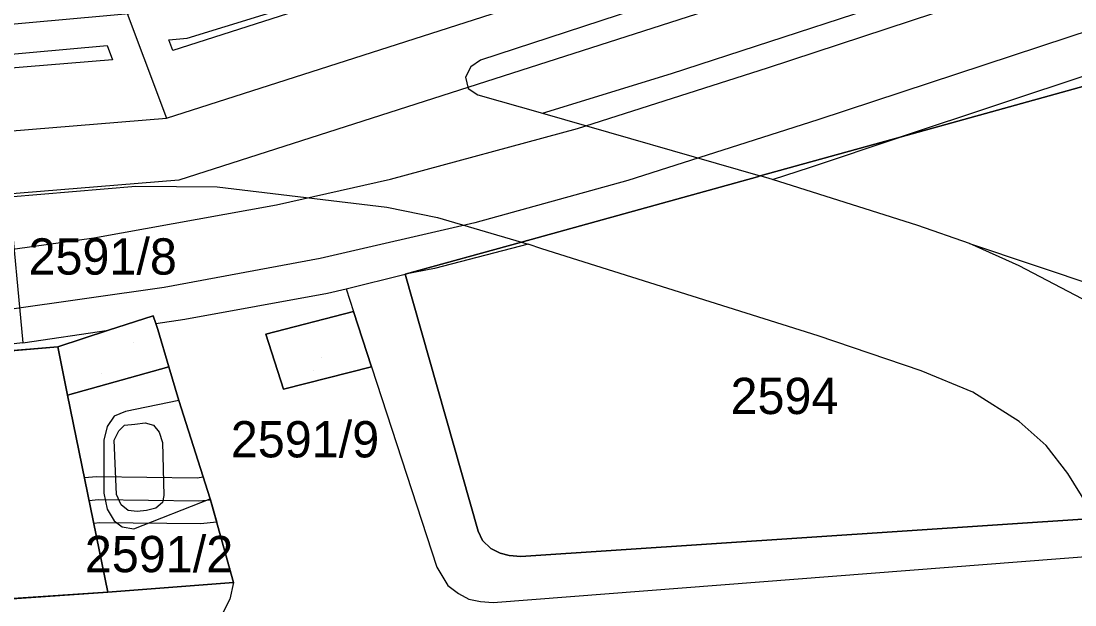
# Model space of a CAD drawing. Extents: x -263423 to -261326, y -1240067 to -1237864.
# Drawn here: x -262797.7 to -262739.6, y -1240038.8 to -1240006.6 of the extents above; entities that cross this region are included whole.
import ezdxf

# ---------------------------------------------------------------- set-up
doc = ezdxf.new("R2010")
doc.units = 0
for name, color, linetype in [('body_kn', 7, 'Continuous'), ('kladpar_druhypozemkov', 7, 'Continuous'), ('kladpar_hranice', 7, 'Continuous'), ('kladpar_parcelnecisla', 7, 'Continuous'), ('kladpar_plochy', 7, 'Continuous'), ('kladpar_sipky', 7, 'Continuous'), ('linie', 7, 'Continuous'), ('tarchy_linie', 7, 'Continuous'), ('zappar_hrandruhpozemk', 7, 'Continuous')]:
    doc.layers.add(name, color=color, linetype=linetype)

msp = doc.modelspace()

# ---------------------------------------------------------------- linework, layer by layer
at = {"layer": 'body_kn'}
for p, q in [((-262792.98, -1240007.92), (-262792.98, -1240007.92)), ((-262789.57, -1240007.62), (-262789.57, -1240007.62)), ((-262788.57, -1240007.52), (-262788.57, -1240007.52)), ((-262740.02, -1240007.49), (-262740.02, -1240007.49)), ((-262789.35, -1240008.2), (-262789.35, -1240008.2)), ((-262789.35, -1240008.2), (-262789.35, -1240008.2)), ((-262792.68, -1240008.72), (-262792.68, -1240008.72)), ((-262772.93, -1240009.1), (-262772.93, -1240009.1)), ((-262772.39, -1240008.74), (-262772.39, -1240008.74)), ((-262773.23, -1240009.67), (-262773.23, -1240009.67)), ((-262761.86, -1240009.47), (-262761.86, -1240009.47)), ((-262756.57, -1240009.16), (-262756.57, -1240009.16)), ((-262773.08, -1240010.29), (-262773.08, -1240010.29)), ((-262772.55, -1240010.65), (-262772.55, -1240010.65)), ((-262789.71, -1240011.94), (-262789.71, -1240011.94)), ((-262768.97, -1240011.65), (-262768.97, -1240011.65)), ((-262768.97, -1240011.65), (-262768.97, -1240011.65)), ((-262753.79, -1240012.03), (-262753.79, -1240012.03)), ((-262767.05, -1240012.5), (-262767.05, -1240012.5)), ((-262749.26, -1240012.98), (-262749.26, -1240012.98)), ((-262754.2, -1240014.63), (-262754.2, -1240014.63)), ((-262789.03, -1240015.36), (-262789.03, -1240015.36)), ((-262777.35, -1240015.29), (-262777.35, -1240015.29)), ((-262764.27, -1240015.38), (-262764.27, -1240015.38)), ((-262757.12, -1240015.16), (-262757.12, -1240015.16)), ((-262756.97, -1240015.12), (-262756.97, -1240015.12)), ((-262756.29, -1240015.32), (-262756.29, -1240015.32)), ((-262756.29, -1240015.32), (-262756.29, -1240015.32)), ((-262791.39, -1240015.68), (-262791.39, -1240015.68)), ((-262786.92, -1240015.72), (-262786.92, -1240015.72)), ((-262783.65, -1240016.71), (-262783.65, -1240016.71)), ((-262777.56, -1240016.84), (-262777.56, -1240016.84)), ((-262774.77, -1240017.41), (-262774.77, -1240017.41)), ((-262772.7, -1240017.71), (-262772.7, -1240017.71)), ((-262748.28, -1240017.86), (-262748.28, -1240017.86)), ((-262793.71, -1240018.53), (-262793.71, -1240018.53)), ((-262770.14, -1240018.77), (-262770.14, -1240018.77)), ((-262770.14, -1240018.77), (-262770.14, -1240018.77)), ((-262769.77, -1240018.88), (-262769.77, -1240018.88)), ((-262745.43, -1240018.84), (-262745.43, -1240018.84)), ((-262745.43, -1240018.84), (-262745.43, -1240018.84)), ((-262769.01, -1240019.14), (-262769.01, -1240019.14)), ((-262781.23, -1240019.68), (-262781.23, -1240019.68)), ((-262742.7, -1240020.08), (-262742.7, -1240020.08)), ((-262776.55, -1240020.54), (-262776.55, -1240020.54)), ((-262774.94, -1240020.23), (-262774.94, -1240020.23)), ((-262789.83, -1240021.28), (-262789.83, -1240021.28)), ((-262780.83, -1240021.58), (-262780.83, -1240021.58)), ((-262779.8, -1240021.35), (-262779.8, -1240021.35)), ((-262779.8, -1240021.35), (-262779.8, -1240021.35)), ((-262790.44, -1240022.84), (-262790.44, -1240022.84)), ((-262788.69, -1240023.02), (-262788.69, -1240023.02)), ((-262779.4, -1240022.59), (-262779.4, -1240022.59)), ((-262792.9, -1240023.63), (-262792.9, -1240023.63)), ((-262790.3, -1240023.25), (-262790.3, -1240023.25)), ((-262790.3, -1240023.25), (-262790.3, -1240023.25)), ((-262790.19, -1240023.58), (-262790.19, -1240023.58)), ((-262784.24, -1240023.84), (-262784.24, -1240023.84)), ((-262784.24, -1240023.84), (-262784.24, -1240023.84)), ((-262753.78, -1240023.94), (-262753.78, -1240023.94)), ((-262797.62, -1240024.33), (-262797.62, -1240024.33)), ((-262797.62, -1240024.33), (-262797.62, -1240024.33)), ((-262795.7, -1240024.54), (-262795.7, -1240024.54)), ((-262795.7, -1240024.54), (-262795.7, -1240024.54)), ((-262789.57, -1240025.65), (-262789.57, -1240025.65)), ((-262778.41, -1240025.64), (-262778.41, -1240025.64)), ((-262778.41, -1240025.64), (-262778.41, -1240025.64)), ((-262748.1, -1240025.86), (-262748.1, -1240025.86)), ((-262783.25, -1240026.88), (-262783.25, -1240026.88)), ((-262745.25, -1240027.04), (-262745.25, -1240027.04)), ((-262795.16, -1240027.21), (-262795.16, -1240027.21)), ((-262795.16, -1240027.21), (-262795.16, -1240027.21)), ((-262789.03, -1240027.5), (-262789.03, -1240027.5)), ((-262789.03, -1240027.5), (-262789.03, -1240027.5)), ((-262791.96, -1240028.1), (-262791.96, -1240028.1)), ((-262792.6, -1240028.36), (-262792.6, -1240028.36)), ((-262792.02, -1240028.86), (-262792.02, -1240028.86)), ((-262791.45, -1240028.8), (-262791.45, -1240028.8)), ((-262791.45, -1240028.8), (-262791.45, -1240028.8)), ((-262790.88, -1240028.74), (-262790.88, -1240028.74)), ((-262790.43, -1240028.86), (-262790.43, -1240028.86)), ((-262742.69, -1240028.66), (-262742.69, -1240028.66)), ((-262792.98, -1240028.93), (-262792.98, -1240028.93)), ((-262792.34, -1240029.18), (-262792.34, -1240029.18)), ((-262790.11, -1240029.25), (-262790.11, -1240029.25)), ((-262793.17, -1240029.69), (-262793.17, -1240029.69)), ((-262792.6, -1240029.69), (-262792.6, -1240029.69)), ((-262789.92, -1240029.82), (-262789.92, -1240029.82)), ((-262741.21, -1240029.98), (-262741.21, -1240029.98)), ((-262794.23, -1240031.75), (-262794.23, -1240031.75)), ((-262794.23, -1240031.75), (-262794.23, -1240031.75)), ((-262793.56, -1240031.7), (-262793.56, -1240031.7)), ((-262788.02, -1240031.76), (-262788.02, -1240031.76)), ((-262787.69, -1240031.72), (-262787.69, -1240031.72)), ((-262740.01, -1240031.52), (-262740.01, -1240031.52)), ((-262793.17, -1240032.61), (-262793.17, -1240032.61)), ((-262792.47, -1240032.68), (-262792.47, -1240032.68)), ((-262789.86, -1240032.74), (-262789.86, -1240032.74)), ((-262787.3, -1240032.93), (-262787.3, -1240032.93)), ((-262793.98, -1240033.01), (-262793.98, -1240033.01)), ((-262793.98, -1240033.01), (-262793.98, -1240033.01)), ((-262793.48, -1240032.97), (-262793.48, -1240032.97)), ((-262792.98, -1240033.5), (-262792.98, -1240033.5)), ((-262792.21, -1240033.25), (-262792.21, -1240033.25)), ((-262790.3, -1240033.44), (-262790.3, -1240033.44)), ((-262789.92, -1240033.12), (-262789.92, -1240033.12)), ((-262787.92, -1240033.03), (-262787.92, -1240033.03)), ((-262787.29, -1240032.98), (-262787.29, -1240032.98)), ((-262791.83, -1240033.57), (-262791.83, -1240033.57)), ((-262791.32, -1240033.63), (-262791.32, -1240033.63)), ((-262790.81, -1240033.57), (-262790.81, -1240033.57)), ((-262793.72, -1240034.28), (-262793.72, -1240034.28)), ((-262793.41, -1240034.25), (-262793.41, -1240034.25)), ((-262792.59, -1240034.14), (-262792.59, -1240034.14)), ((-262792.15, -1240034.46), (-262792.15, -1240034.46)), ((-262791.51, -1240034.58), (-262791.51, -1240034.58)), ((-262787.83, -1240034.31), (-262787.83, -1240034.31)), ((-262786.94, -1240034.21), (-262786.94, -1240034.21)), ((-262772.53, -1240034.71), (-262772.53, -1240034.71)), ((-262772.28, -1240035.22), (-262772.28, -1240035.22)), ((-262771.83, -1240035.66), (-262771.83, -1240035.66)), ((-262771.32, -1240035.92), (-262771.32, -1240035.92)), ((-262770.81, -1240036.05), (-262770.81, -1240036.05)), ((-262770.18, -1240036.11), (-262770.18, -1240036.11)), ((-262774.81, -1240036.69), (-262774.81, -1240036.69)), ((-262786.02, -1240037.53), (-262786.02, -1240037.53)), ((-262786.02, -1240037.53), (-262786.02, -1240037.53)), ((-262792.94, -1240038.08), (-262792.94, -1240038.08)), ((-262774.19, -1240037.7), (-262774.19, -1240037.7)), ((-262773.61, -1240038.14), (-262773.61, -1240038.14)), ((-262786.22, -1240038.46), (-262786.22, -1240038.46)), ((-262773.04, -1240038.46), (-262773.04, -1240038.46)), ((-262772.4, -1240038.59), (-262772.4, -1240038.59)), ((-262771.7, -1240038.65), (-262771.7, -1240038.65))]:
    msp.add_line(p, q, dxfattribs=at)
at = {"layer": 'kladpar_druhypozemkov'}
for p, q in [((-262781.14, -1240025.15), (-262781.14, -1240025.15)), ((-262793.28, -1240026.01), (-262793.28, -1240026.01)), ((-262755.64, -1240026.56), (-262755.64, -1240026.56)), ((-262788.6, -1240035.25), (-262788.6, -1240035.25))]:
    msp.add_line(p, q, dxfattribs=at)
at = {"layer": 'kladpar_hranice'}
for points in [[(-262728.66, -1240007.27), (-262730.48, -1240021.23), (-262730.55, -1240021.78), (-262730.58, -1240022.04), (-262730.81, -1240023.78), (-262731.33, -1240027.7), (-262731.65, -1240030.15), (-262731.68, -1240030.4), (-262731.69, -1240030.45), (-262732.09, -1240033.57), (-262738.53, -1240034), (-262738.63, -1240034.01), (-262770.18, -1240036.11), (-262770.81, -1240036.05), (-262771.32, -1240035.92), (-262771.83, -1240035.66), (-262772.28, -1240035.22), (-262772.53, -1240034.71), (-262776.55, -1240020.54), (-262770.14, -1240018.77), (-262757.12, -1240015.16), (-262756.97, -1240015.12), (-262749.26, -1240012.98), (-262728.66, -1240007.27)], [(-262732.09, -1240033.57), (-262731.69, -1240030.45), (-262731.68, -1240030.4), (-262731.65, -1240030.15), (-262731.33, -1240027.7), (-262730.81, -1240023.78), (-262730.58, -1240022.04), (-262730.55, -1240021.78), (-262730.48, -1240021.23), (-262728.66, -1240007.27), (-262749.26, -1240012.98), (-262756.97, -1240015.12), (-262757.12, -1240015.16), (-262770.14, -1240018.77), (-262776.55, -1240020.54), (-262772.53, -1240034.71), (-262772.28, -1240035.22), (-262771.83, -1240035.66), (-262771.32, -1240035.92), (-262770.81, -1240036.05), (-262770.18, -1240036.11), (-262738.63, -1240034.01), (-262738.53, -1240034), (-262732.09, -1240033.57)], [(-262868.76, -1240043.15), (-262792.94, -1240038.08), (-262786.02, -1240037.53), (-262787.3, -1240032.93), (-262789.03, -1240027.5), (-262789.57, -1240025.65), (-262790.19, -1240023.58), (-262790.3, -1240023.25), (-262790.44, -1240022.84), (-262792.9, -1240023.63), (-262795.7, -1240024.54), (-262822.11, -1240026.78), (-262869.91, -1240030.83), (-262878.29, -1240031.54), (-262880.31, -1240031.71), (-262939.63, -1240036.72), (-262939.77, -1240036.73), (-262939.77, -1240037.06), (-262939.77, -1240047.97), (-262868.76, -1240043.15)], [(-262795.7, -1240024.54), (-262792.9, -1240023.63), (-262790.44, -1240022.84), (-262790.3, -1240023.25), (-262790.19, -1240023.58), (-262789.57, -1240025.65), (-262795.16, -1240027.21), (-262795.7, -1240024.54)], [(-262784.24, -1240023.84), (-262779.4, -1240022.59), (-262778.41, -1240025.64), (-262783.25, -1240026.88), (-262784.24, -1240023.84)], [(-262784.24, -1240023.84), (-262783.25, -1240026.88), (-262778.41, -1240025.64), (-262779.4, -1240022.59), (-262784.24, -1240023.84)], [(-262869.91, -1240030.83), (-262822.11, -1240026.78), (-262795.7, -1240024.54), (-262795.16, -1240027.21), (-262792.94, -1240038.08), (-262868.76, -1240043.15), (-262939.77, -1240047.97), (-262939.77, -1240037.06), (-262939.77, -1240036.73), (-262939.63, -1240036.72), (-262880.31, -1240031.71), (-262878.29, -1240031.54), (-262869.91, -1240030.83)], [(-262795.16, -1240027.21), (-262789.57, -1240025.65), (-262789.03, -1240027.5), (-262787.3, -1240032.93), (-262786.02, -1240037.53), (-262792.94, -1240038.08), (-262795.16, -1240027.21)]]:
    msp.add_lwpolyline(points, dxfattribs=at)
at = {"layer": 'kladpar_plochy'}
for p, q in [((-262728.66, -1240007.27), (-262749.26, -1240012.98)), ((-262749.26, -1240012.98), (-262756.97, -1240015.12)), ((-262757.12, -1240015.16), (-262770.14, -1240018.77)), ((-262756.97, -1240015.12), (-262757.12, -1240015.16)), ((-262770.14, -1240018.77), (-262776.55, -1240020.54)), ((-262776.55, -1240020.54), (-262772.53, -1240034.71)), ((-262790.44, -1240022.84), (-262792.9, -1240023.63)), ((-262790.3, -1240023.25), (-262790.44, -1240022.84)), ((-262779.4, -1240022.59), (-262784.24, -1240023.84)), ((-262778.41, -1240025.64), (-262779.4, -1240022.59)), ((-262792.9, -1240023.63), (-262795.7, -1240024.54)), ((-262790.19, -1240023.58), (-262790.3, -1240023.25)), ((-262789.57, -1240025.65), (-262790.19, -1240023.58)), ((-262784.24, -1240023.84), (-262783.25, -1240026.88)), ((-262795.7, -1240024.54), (-262822.11, -1240026.78)), ((-262789.03, -1240027.5), (-262789.57, -1240025.65)), ((-262783.25, -1240026.88), (-262778.41, -1240025.64)), ((-262787.3, -1240032.93), (-262789.03, -1240027.5)), ((-262786.02, -1240037.53), (-262787.3, -1240032.93)), ((-262770.18, -1240036.11), (-262738.63, -1240034.01)), ((-262772.53, -1240034.71), (-262772.28, -1240035.22)), ((-262772.28, -1240035.22), (-262771.83, -1240035.66)), ((-262771.83, -1240035.66), (-262771.32, -1240035.92)), ((-262771.32, -1240035.92), (-262770.81, -1240036.05)), ((-262770.81, -1240036.05), (-262770.18, -1240036.11)), ((-262792.94, -1240038.08), (-262786.02, -1240037.53)), ((-262868.76, -1240043.15), (-262792.94, -1240038.08))]:
    msp.add_line(p, q, dxfattribs=at)
for points in [[(-262728.66, -1240007.27), (-262730.48, -1240021.23), (-262730.55, -1240021.78), (-262730.58, -1240022.04), (-262730.81, -1240023.78), (-262731.33, -1240027.7), (-262731.65, -1240030.15), (-262731.68, -1240030.4), (-262731.69, -1240030.45), (-262732.09, -1240033.57), (-262738.53, -1240034), (-262738.63, -1240034.01), (-262770.18, -1240036.11), (-262770.81, -1240036.05), (-262771.32, -1240035.92), (-262771.83, -1240035.66), (-262772.28, -1240035.22), (-262772.53, -1240034.71), (-262776.55, -1240020.54), (-262770.14, -1240018.77), (-262757.12, -1240015.16), (-262756.97, -1240015.12), (-262749.26, -1240012.98)], [(-262795.7, -1240024.54), (-262792.9, -1240023.63), (-262790.44, -1240022.84), (-262790.3, -1240023.25), (-262790.19, -1240023.58), (-262789.57, -1240025.65), (-262795.16, -1240027.21)], [(-262784.24, -1240023.84), (-262779.4, -1240022.59), (-262778.41, -1240025.64), (-262783.25, -1240026.88)], [(-262869.91, -1240030.83), (-262822.11, -1240026.78), (-262795.7, -1240024.54), (-262795.16, -1240027.21), (-262792.94, -1240038.08), (-262868.76, -1240043.15), (-262939.77, -1240047.97), (-262939.77, -1240037.06), (-262939.77, -1240036.73), (-262939.63, -1240036.72), (-262880.31, -1240031.71), (-262878.29, -1240031.54)], [(-262795.16, -1240027.21), (-262789.57, -1240025.65), (-262789.03, -1240027.5), (-262787.3, -1240032.93), (-262786.02, -1240037.53), (-262792.94, -1240038.08)]]:
    msp.add_lwpolyline(points, close=True, dxfattribs=at)
at = {"layer": 'kladpar_sipky'}
for p, q in [((-262791.52, -1240024.31), (-262791.52, -1240024.31)), ((-262781.63, -1240025.86), (-262781.63, -1240025.86))]:
    msp.add_line(p, q, dxfattribs=at)
at = {"layer": 'linie'}
for points in [[(-262703.5, -1239995.46), (-262740.02, -1240007.49), (-262753.79, -1240012.03), (-262764.27, -1240015.38), (-262772.7, -1240017.71), (-262781.23, -1240019.68), (-262789.83, -1240021.28), (-262798.49, -1240022.5), (-262809.44, -1240023.61), (-262919.99, -1240033.8), (-262931.04, -1240034.72), (-262939.35, -1240035.09), (-262947.68, -1240035.12), (-262955.99, -1240034.8), (-262964.29, -1240034.15), (-262975.3, -1240032.85), (-263221.73, -1240001.53)], [(-263207.05, -1240000.27), (-262981.57, -1240028.93), (-262968.8, -1240030.48), (-262962.8, -1240031.08), (-262957.19, -1240031.52), (-262950.54, -1240031.84), (-262944.24, -1240031.95), (-262936.75, -1240031.81), (-262931.29, -1240031.53), (-262920.33, -1240030.62), (-262811.51, -1240020.59), (-262800.56, -1240019.48), (-262793.71, -1240018.53), (-262783.65, -1240016.71), (-262777.35, -1240015.29), (-262767.05, -1240012.5), (-262756.57, -1240009.16), (-262739.52, -1240003.54)]]:
    msp.add_lwpolyline(points, dxfattribs=at)
at = {"layer": 'tarchy_linie'}
msp.add_line((-262793.53, -1240001.71), (-262789.71, -1240011.94), dxfattribs=at)
for points in [[(-263147.28, -1239996.85), (-263030.94, -1240011.19), (-262952.34, -1240022.76), (-262895.18, -1240015.48), (-262788.72, -1240005.88), (-262678.82, -1239972.02)], [(-263294.33, -1239987.55), (-263230.04, -1239998.95), (-263150.79, -1240013.01), (-263089.3, -1240012.13), (-263026.76, -1240020.2), (-262979.54, -1240026.3), (-262896.92, -1240020.74), (-262789.71, -1240011.94), (-262677.55, -1239975.98)], [(-262672.97, -1239978.12), (-262789.03, -1240015.36), (-262896.7, -1240024.18), (-262950.5, -1240027.8), (-262948.94, -1240055.42), (-262945.36, -1240056.03), (-262890.34, -1240052.15), (-262834.9, -1240047.57), (-262778.77, -1240043.22), (-262727.63, -1240040.12)], [(-262789.35, -1240008.2), (-262789.57, -1240007.62), (-262788.57, -1240007.52), (-262755.28, -1239997.28), (-262789.35, -1240008.2)], [(-262893.92, -1240017.02), (-262792.98, -1240007.92), (-262792.68, -1240008.72), (-262893.92, -1240017.02)], [(-262794.23, -1240031.75), (-262793.56, -1240031.7), (-262788.02, -1240031.76), (-262787.69, -1240031.72), (-262787.3, -1240032.93), (-262787.29, -1240032.98), (-262786.94, -1240034.21), (-262787.83, -1240034.31), (-262793.41, -1240034.25), (-262793.72, -1240034.28), (-262793.98, -1240033.01), (-262794.23, -1240031.75)], [(-262793.98, -1240033.01), (-262793.48, -1240032.97), (-262787.92, -1240033.03), (-262787.29, -1240032.98)]]:
    msp.add_lwpolyline(points, dxfattribs=at)
at = {"layer": 'zappar_hrandruhpozemk'}
for p, q in [((-262768.97, -1240011.65), (-262756.97, -1240015.12)), ((-262754.2, -1240014.63), (-262749.26, -1240012.98)), ((-262756.29, -1240015.32), (-262754.2, -1240014.63)), ((-262786.92, -1240015.72), (-262777.56, -1240016.84)), ((-262770.14, -1240018.77), (-262769.77, -1240018.88)), ((-262745.43, -1240018.84), (-262734.58, -1240022.5)), ((-262753.78, -1240023.94), (-262769.01, -1240019.14)), ((-262779.8, -1240021.35), (-262776.55, -1240020.54)), ((-262788.69, -1240023.02), (-262780.83, -1240021.58)), ((-262780.83, -1240021.58), (-262779.8, -1240021.35)), ((-262779.8, -1240021.35), (-262779.4, -1240022.59)), ((-262790.3, -1240023.25), (-262788.69, -1240023.02)), ((-262797.62, -1240024.33), (-262792.9, -1240023.63)), ((-262778.41, -1240025.64), (-262774.81, -1240036.69)), ((-262793.17, -1240029.69), (-262793.17, -1240032.61)), ((-262792.47, -1240032.68), (-262792.6, -1240029.69)), ((-262771.7, -1240038.65), (-262737.77, -1240036))]:
    msp.add_line(p, q, dxfattribs=at)
for points in [[(-262681.51, -1239991.91), (-262681.98, -1239991.97), (-262682.82, -1239992.1), (-262684.7, -1239992.53), (-262687.84, -1239993.2), (-262697.88, -1239996.01), (-262706.61, -1239998.79), (-262749.26, -1240012.98)], [(-262746.87, -1240000.38), (-262772.39, -1240008.74), (-262772.93, -1240009.1), (-262773.23, -1240009.67), (-262773.08, -1240010.29), (-262772.55, -1240010.65), (-262768.97, -1240011.65), (-262761.86, -1240009.47), (-262745.6, -1240004.16)], [(-262737.53, -1240023.02), (-262739.23, -1240021.9), (-262742.7, -1240020.08), (-262745.43, -1240018.84), (-262748.28, -1240017.86), (-262756.29, -1240015.32), (-262756.97, -1240015.12)], [(-262798.39, -1240016.27), (-262791.39, -1240015.68), (-262786.92, -1240015.72)], [(-262804.7, -1240016.86), (-262798.39, -1240016.27), (-262797.62, -1240024.33), (-262803.45, -1240024.99), (-262822.11, -1240026.78)], [(-262777.56, -1240016.84), (-262774.77, -1240017.41), (-262770.14, -1240018.77)], [(-262769.01, -1240019.14), (-262769.77, -1240018.88), (-262774.94, -1240020.23), (-262776.55, -1240020.54)], [(-262738.63, -1240034.01), (-262738.93, -1240033.28), (-262740.01, -1240031.52), (-262741.21, -1240029.98), (-262742.69, -1240028.66), (-262745.25, -1240027.04), (-262748.1, -1240025.86), (-262753.78, -1240023.94)], [(-262789.03, -1240027.5), (-262791.96, -1240028.1), (-262792.6, -1240028.36), (-262792.98, -1240028.93), (-262793.17, -1240029.69)], [(-262792.6, -1240029.69), (-262792.34, -1240029.18), (-262792.02, -1240028.86), (-262791.45, -1240028.8)], [(-262791.45, -1240028.8), (-262790.88, -1240028.74), (-262790.43, -1240028.86), (-262790.11, -1240029.25), (-262789.92, -1240029.82), (-262789.86, -1240032.74), (-262789.92, -1240033.12), (-262790.3, -1240033.44), (-262790.81, -1240033.57), (-262791.32, -1240033.63), (-262791.83, -1240033.57), (-262792.21, -1240033.25), (-262792.47, -1240032.68)], [(-262793.17, -1240032.61), (-262792.98, -1240033.5), (-262792.59, -1240034.14), (-262792.15, -1240034.46), (-262791.51, -1240034.58), (-262787.3, -1240032.93)], [(-262774.81, -1240036.69), (-262774.19, -1240037.7), (-262773.61, -1240038.14), (-262773.04, -1240038.46), (-262772.4, -1240038.59), (-262771.7, -1240038.65)], [(-262786.02, -1240037.53), (-262786.22, -1240038.46), (-262786.61, -1240039.22), (-262787.18, -1240039.73), (-262787.82, -1240040.11), (-262788.58, -1240040.36), (-262789.41, -1240040.49)]]:
    msp.add_lwpolyline(points, dxfattribs=at)

# ---------------------------------------------------------------- texts
at = {"layer": 'kladpar_parcelnecisla'}
for s, p in [('2591/8', (-262797.316, -1240020.56)), ('2594', (-262758.612, -1240028.25)), ('2591/9', (-262786.162, -1240030.64)), ('2591/2', (-262794.209, -1240036.97))]:
    msp.add_text(s, height=2, dxfattribs=at).set_placement(p)

doc.saveas('drawing.dxf')
